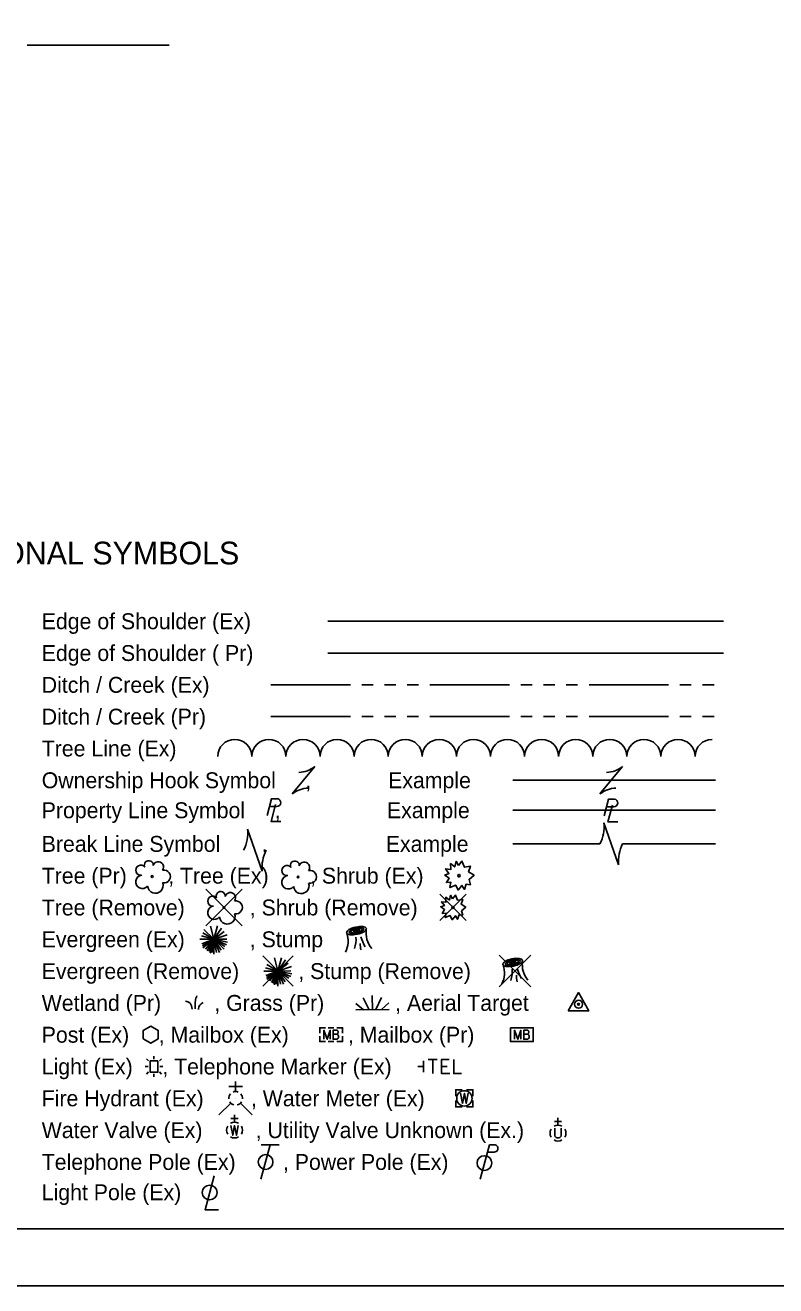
# Model space of a CAD drawing. Extents: x 0 to 34, y 0 to 22.
# Drawn here: x 7.73 to 14.34, y 0 to 11.1 of the extents above; entities that cross this region are included whole.
import ezdxf

# ---------------------------------------------------------------- set-up
doc = ezdxf.new("R2010")
doc.units = 0
for name, color, linetype in [('SH_Border', 7, 'Continuous'), ('SH_Cut_Line', 7, 'Continuous'), ('SH_Data', 7, 'Continuous'), ('SH_Text', 7, 'Continuous')]:
    doc.layers.add(name, color=color, linetype=linetype)

msp = doc.modelspace()

# ---------------------------------------------------------------- linework, layer by layer
at = {"layer": 'SH_Border'}
msp.add_lwpolyline([(1.5, 21.5), (33.5, 21.5), (33.5, 0.5), (1.5, 0.5)], close=True, dxfattribs=at)
at = {"layer": 'SH_Cut_Line'}
msp.add_lwpolyline([(0, 0), (34, 0), (34, 22), (0, 22)], close=True, dxfattribs=at)
at = {"layer": 'SH_Data'}
msp.add_line((9, 10.922), (7.75, 10.922), dxfattribs=at)
at = {"layer": 'SH_Text'}
for p, q in [((10.395, 5.85), (13.878, 5.85)), ((10.395, 5.57), (13.878, 5.57)), ((9.894, 5.29), (10.594, 5.29)), ((10.694, 5.29), (10.794, 5.29)), ((10.894, 5.29), (10.994, 5.29)), ((11.094, 5.29), (11.194, 5.29)), ((11.294, 5.29), (11.994, 5.29)), ((12.094, 5.29), (12.194, 5.29)), ((12.294, 5.29), (12.394, 5.29)), ((12.494, 5.29), (12.594, 5.29)), ((12.694, 5.29), (13.394, 5.29)), ((13.494, 5.29), (13.594, 5.29)), ((13.694, 5.29), (13.794, 5.29)), ((9.894, 5.01), (10.594, 5.01)), ((10.694, 5.01), (10.794, 5.01)), ((10.894, 5.01), (10.994, 5.01)), ((11.094, 5.01), (11.194, 5.01)), ((11.294, 5.01), (11.994, 5.01)), ((12.094, 5.01), (12.194, 5.01)), ((12.294, 5.01), (12.394, 5.01)), ((12.494, 5.01), (12.594, 5.01)), ((12.694, 5.01), (13.394, 5.01)), ((13.494, 5.01), (13.594, 5.01)), ((13.694, 5.01), (13.794, 5.01)), ((10.082, 4.33), (10.282, 4.57)), ((12.79, 4.33), (12.99, 4.57)), ((10.182, 4.45), (10.182, 4.45)), ((12.024, 4.45), (13.807, 4.45)), ((12.89, 4.45), (12.89, 4.45)), ((9.882, 4.219), (9.947, 4.219)), ((9.922, 4.188), (9.922, 4.188)), ((12.024, 4.186), (13.807, 4.186)), ((12.848, 4.215), (12.912, 4.215)), ((12.888, 4.184), (12.888, 4.184)), ((9.689, 4.019), (9.819, 3.651)), ((12.825, 4.075), (12.955, 3.706)), ((12.024, 3.89), (12.79, 3.89)), ((12.89, 3.89), (12.89, 3.89)), ((12.99, 3.89), (13.807, 3.89)), ((9.754, 3.835), (9.754, 3.835)), ((9.322, 3.491), (9.643, 3.17)), ((9.643, 3.491), (9.322, 3.17)), ((11.381, 3.446), (11.613, 3.215)), ((11.613, 3.446), (11.381, 3.215)), ((9.482, 3.33), (9.482, 3.33)), ((11.497, 3.33), (11.497, 3.33)), ((9.393, 3.05), (9.295, 3.108)), ((9.393, 3.05), (9.306, 3.137)), ((9.393, 3.05), (9.362, 3.166)), ((9.393, 3.05), (9.424, 3.168)), ((9.393, 3.05), (9.459, 3.147)), ((9.393, 3.05), (9.484, 3.12)), ((9.27, 3.05), (9.393, 3.05)), ((9.393, 3.05), (9.283, 3.08)), ((9.393, 3.05), (9.286, 3.011)), ((9.393, 3.05), (9.293, 2.993)), ((9.393, 3.05), (9.295, 2.975)), ((9.393, 3.05), (9.319, 2.964)), ((9.393, 3.05), (9.335, 2.95)), ((9.393, 3.05), (9.351, 2.942)), ((9.393, 3.05), (9.361, 2.929)), ((9.393, 3.05), (9.379, 2.935)), ((9.393, 3.05), (9.511, 3.09)), ((9.393, 3.05), (9.506, 3.052)), ((9.393, 2.919), (9.393, 3.05)), ((9.393, 3.05), (9.416, 2.934)), ((9.393, 3.05), (9.441, 2.933)), ((9.393, 3.05), (9.456, 2.955)), ((9.393, 3.05), (9.483, 2.962)), ((9.393, 3.05), (9.489, 2.986)), ((9.393, 3.05), (9.505, 3.002)), ((9.393, 3.05), (9.514, 3.026)), ((10.667, 3.05), (10.667, 3.05)), ((9.823, 2.904), (10.091, 2.637)), ((10.091, 2.904), (9.823, 2.637)), ((9.957, 2.77), (9.926, 2.886)), ((9.957, 2.77), (9.988, 2.888)), ((11.903, 2.909), (12.181, 2.631)), ((12.181, 2.909), (11.903, 2.631)), ((9.957, 2.77), (9.847, 2.8)), ((9.957, 2.77), (9.859, 2.828)), ((9.957, 2.77), (9.87, 2.858)), ((9.957, 2.77), (10.023, 2.868)), ((9.957, 2.77), (10.048, 2.841)), ((9.957, 2.77), (10.075, 2.811)), ((9.834, 2.77), (9.957, 2.77)), ((9.957, 2.77), (9.85, 2.731)), ((9.957, 2.77), (9.857, 2.713)), ((9.957, 2.77), (9.859, 2.696)), ((9.957, 2.77), (9.883, 2.684)), ((9.957, 2.77), (9.899, 2.67)), ((9.957, 2.77), (9.915, 2.662)), ((9.957, 2.77), (9.925, 2.649)), ((9.957, 2.77), (9.943, 2.656)), ((9.957, 2.77), (10.07, 2.773)), ((9.957, 2.639), (9.957, 2.77)), ((9.957, 2.77), (9.98, 2.655)), ((9.957, 2.77), (10.005, 2.654)), ((9.957, 2.77), (10.02, 2.676)), ((9.957, 2.77), (10.047, 2.682)), ((9.957, 2.77), (10.053, 2.707)), ((9.957, 2.77), (10.069, 2.722)), ((9.957, 2.77), (10.078, 2.746)), ((9.957, 2.77), (9.957, 2.77)), ((12.042, 2.77), (12.042, 2.77)), ((12.042, 2.77), (12.042, 2.77)), ((10.789, 2.43), (10.787, 2.556)), ((10.71, 2.429), (10.642, 2.486)), ((10.759, 2.43), (10.706, 2.536)), ((10.819, 2.431), (10.868, 2.538)), ((10.867, 2.432), (10.934, 2.491)), ((10.642, 2.428), (10.935, 2.433)), ((10.4, 2.272), (10.45, 2.272)), ((10.4, 2.149), (10.45, 2.149)), ((10.425, 2.21), (10.425, 2.21)), ((12.103, 2.21), (12.103, 2.21)), ((8.817, 1.979), (8.799, 1.998)), ((8.866, 1.994), (8.866, 2.021)), ((8.932, 1.998), (8.914, 1.979)), ((8.814, 1.931), (8.787, 1.931)), ((8.866, 1.93), (8.866, 1.93)), ((8.944, 1.931), (8.918, 1.931)), ((11.238, 1.93), (11.189, 1.93)), ((11.238, 1.88), (11.238, 1.98)), ((8.817, 1.882), (8.799, 1.863)), ((8.866, 1.866), (8.866, 1.84)), ((8.932, 1.863), (8.914, 1.882)), ((9.584, 1.711), (9.584, 1.797)), ((9.644, 1.754), (9.524, 1.754)), ((9.541, 1.608), (9.437, 1.504)), ((9.584, 1.65), (9.584, 1.65)), ((9.584, 1.65), (9.584, 1.65)), ((9.626, 1.608), (9.73, 1.504)), ((11.597, 1.65), (11.597, 1.65)), ((9.606, 1.472), (9.543, 1.472)), ((9.575, 1.44), (9.575, 1.504)), ((12.453, 1.446), (12.389, 1.446)), ((12.421, 1.414), (12.421, 1.478)), ((9.575, 1.37), (9.575, 1.37)), ((12.394, 1.387), (12.394, 1.318)), ((12.421, 1.344), (12.421, 1.344)), ((12.448, 1.387), (12.448, 1.318)), ((9.888, 1.24), (9.807, 0.94)), ((9.968, 1.24), (9.808, 1.24)), ((11.817, 1.24), (11.736, 0.94)), ((11.817, 1.24), (11.859, 1.24)), ((11.8, 1.177), (11.859, 1.177))]:
    msp.add_line(p, q, dxfattribs=at)
for points in [[(9.861, 4.14), (9.9, 4.288), (9.952, 4.288)], [(9.935, 4.236), (9.896, 4.088), (9.983, 4.088)], [(12.827, 4.136), (12.866, 4.284), (12.917, 4.284)], [(12.901, 4.232), (12.861, 4.084), (12.949, 4.084)], [(11.546, 3.701), (11.576, 3.738), (11.597, 3.685), (11.651, 3.694), (11.635, 3.643), (11.682, 3.614), (11.639, 3.577), (11.651, 3.531), (11.614, 3.535), (11.598, 3.489), (11.576, 3.524), (11.542, 3.483), (11.521, 3.527), (11.47, 3.506), (11.479, 3.553), (11.439, 3.549), (11.462, 3.588), (11.424, 3.616), (11.461, 3.63), (11.431, 3.67), (11.477, 3.664), (11.476, 3.716), (11.513, 3.688), (11.524, 3.737), (11.546, 3.701)], [(11.493, 3.407), (11.519, 3.439), (11.537, 3.394), (11.583, 3.401), (11.569, 3.358), (11.609, 3.333), (11.573, 3.302), (11.583, 3.263), (11.551, 3.266), (11.537, 3.227), (11.519, 3.257), (11.49, 3.222), (11.472, 3.26), (11.429, 3.241), (11.437, 3.281), (11.402, 3.278), (11.423, 3.311), (11.39, 3.336), (11.421, 3.347), (11.396, 3.381), (11.435, 3.376), (11.434, 3.42), (11.466, 3.396), (11.475, 3.438), (11.493, 3.407)], [(8.772, 2.173), (8.837, 2.135), (8.902, 2.173), (8.902, 2.248), (8.837, 2.285), (8.772, 2.248), (8.772, 2.173)], [(10.325, 2.223), (10.325, 2.272), (10.374, 2.272)], [(10.361, 2.17), (10.361, 2.25), (10.39, 2.17), (10.417, 2.25), (10.417, 2.17)], [(10.476, 2.214), (10.48, 2.217), (10.481, 2.219), (10.483, 2.221), (10.483, 2.222), (10.485, 2.225), (10.485, 2.226), (10.487, 2.231), (10.487, 2.233), (10.487, 2.235), (10.486, 2.239), (10.485, 2.242), (10.483, 2.245), (10.48, 2.247), (10.477, 2.249), (10.476, 2.249), (10.473, 2.25), (10.442, 2.25), (10.442, 2.17), (10.476, 2.17), (10.481, 2.173), (10.485, 2.176), (10.488, 2.181), (10.49, 2.187), (10.49, 2.192), (10.49, 2.196), (10.489, 2.2), (10.487, 2.206), (10.483, 2.209), (10.476, 2.214), (10.442, 2.214)], [(10.476, 2.272), (10.525, 2.272), (10.525, 2.223)], [(12.039, 2.17), (12.039, 2.25), (12.068, 2.17), (12.095, 2.25), (12.095, 2.17)], [(12.155, 2.214), (12.158, 2.217), (12.16, 2.219), (12.161, 2.221), (12.161, 2.222), (12.163, 2.225), (12.163, 2.226), (12.165, 2.231), (12.165, 2.233), (12.165, 2.235), (12.164, 2.239), (12.163, 2.242), (12.161, 2.245), (12.158, 2.247), (12.155, 2.249), (12.154, 2.249), (12.151, 2.25), (12.12, 2.25), (12.12, 2.17), (12.155, 2.17), (12.159, 2.173), (12.163, 2.176), (12.166, 2.181), (12.168, 2.187), (12.168, 2.192), (12.168, 2.196), (12.167, 2.2), (12.165, 2.206), (12.161, 2.209), (12.155, 2.214), (12.12, 2.214)], [(10.374, 2.149), (10.325, 2.149), (10.325, 2.198)], [(10.525, 2.198), (10.525, 2.149), (10.476, 2.149)], [(11.279, 1.993), (11.357, 1.993)], [(11.319, 1.993), (11.319, 1.868)], [(11.464, 1.993), (11.396, 1.993), (11.396, 1.868), (11.469, 1.868)], [(11.396, 1.931), (11.445, 1.931)], [(11.504, 1.993), (11.504, 1.868), (11.571, 1.868)], [(11.577, 1.725), (11.522, 1.725), (11.522, 1.67)], [(11.564, 1.695), (11.581, 1.605), (11.597, 1.695), (11.614, 1.605), (11.631, 1.695)], [(11.672, 1.67), (11.672, 1.725), (11.617, 1.725)], [(11.522, 1.63), (11.522, 1.575), (11.577, 1.575)], [(11.617, 1.575), (11.672, 1.575), (11.672, 1.63)], [(9.543, 1.411), (9.559, 1.325), (9.575, 1.411), (9.591, 1.325), (9.606, 1.411)], [(9.395, 0.969), (9.316, 0.67), (9.434, 0.67)]]:
    msp.add_lwpolyline(points, dxfattribs=at)
for points in [[(12.512, 2.42), (12.692, 2.42), (12.602, 2.581)], [(12.003, 2.272), (12.203, 2.272), (12.203, 2.149), (12.003, 2.149)], [(8.832, 1.88), (8.899, 1.88), (8.899, 1.98), (8.832, 1.98)]]:
    msp.add_lwpolyline(points, close=True, dxfattribs=at)
for centre, radius in [((8.849, 3.602), 0.0084), ((10.134, 3.599), 0.0072), ((11.55, 3.61), 0.0115), ((9.482, 3.33), 0.0072), ((11.497, 3.33), 0.00979), ((12.602, 2.478), 0.035), ((12.602, 2.478), 0.008), ((11.597, 1.65), 0.0675), ((9.848, 1.09), 0.065), ((11.774, 1.08), 0.065), ((9.356, 0.821), 0.065)]:
    msp.add_circle(centre, radius, dxfattribs=at)
for centre, radius, start, end in [((9.577, 4.66), 0.15, 0.0098, 179.9926), ((9.877, 4.66), 0.15, 0.0098, 179.9926), ((10.177, 4.66), 0.15, 0.0098, 179.9926), ((10.477, 4.66), 0.15, 0.0098, 179.9926), ((10.777, 4.66), 0.15, 0.0098, 179.9926), ((11.077, 4.66), 0.15, 0.0098, 179.9926), ((11.377, 4.66), 0.15, 0.0098, 179.9926), ((11.677, 4.66), 0.15, 0.0098, 179.9926), ((11.977, 4.66), 0.15, 0.0098, 179.9926), ((12.277, 4.66), 0.15, 0.0098, 179.9926), ((12.577, 4.66), 0.15, 0.0098, 179.9926), ((12.877, 4.66), 0.15, 0.0098, 179.9926), ((13.177, 4.66), 0.15, 0.0098, 179.9926), ((13.477, 4.66), 0.15, 0.0098, 179.9926), ((13.777, 4.66), 0.15, 89.9955, 179.9926), ((10.124, 4.785), 0.267, 273.6945, 306.337), ((12.832, 4.785), 0.267, 273.6945, 306.337), ((10.24, 4.115), 0.267, 93.6945, 126.337), ((12.948, 4.115), 0.267, 93.6945, 126.337), ((9.947, 4.254), 0.0345, 270.471, 81.3281), ((12.912, 4.25), 0.0345, 270.471, 81.3281), ((9.357, 3.987), 0.334, 332.9422, 5.5848), ((12.493, 4.042), 0.334, 332.9422, 5.5848), ((13.287, 3.739), 0.334, 152.9422, 185.5848), ((10.151, 3.683), 0.334, 152.9422, 185.5848), ((8.75, 3.658), 0.0441, 39.0625, 279.5412), ((8.82, 3.703), 0.0395, 354.0047, 205.9741), ((8.904, 3.687), 0.0466, 323.83, 165.0376), ((10.035, 3.655), 0.0441, 39.0625, 279.5412), ((10.105, 3.7), 0.0395, 354.0047, 205.9741), ((10.189, 3.684), 0.0466, 323.83, 165.0376), ((8.764, 3.556), 0.0592, 96.1722, 320.5737), ((8.953, 3.603), 0.0574, 259.1453, 101.4596), ((10.048, 3.552), 0.0592, 96.1722, 320.5737), ((10.238, 3.6), 0.0574, 259.1453, 101.4596), ((8.878, 3.524), 0.0685, 184.9476, 19.4572), ((9.453, 3.431), 0.0395, 354.0047, 205.9741), ((9.537, 3.415), 0.0466, 323.83, 165.0376), ((10.162, 3.521), 0.0685, 184.9476, 19.4572), ((9.397, 3.284), 0.0592, 96.1722, 320.5737), ((9.383, 3.386), 0.0441, 39.0625, 279.5412), ((9.586, 3.331), 0.0574, 259.1453, 101.4596), ((9.511, 3.252), 0.0685, 184.9476, 19.4572), ((10.947, 3.107), 0.215, 171.4106, 219.9194), ((10.375, 3.033), 0.2, 331.5338, 20.9269), ((10.391, 3.052), 0.253, 340.7938, 3.5481), ((10.862, 3.01), 0.182, 178.7926, 197.1224), ((10.992, 3.153), 0.316, 194.9653, 212.1216), ((11.751, 2.753), 0.2, 331.5338, 20.9269), ((11.766, 2.772), 0.253, 340.7938, 3.5481), ((12.368, 2.873), 0.316, 194.9653, 212.1216), ((12.322, 2.827), 0.215, 171.4106, 219.9194), ((12.237, 2.73), 0.182, 178.7926, 197.1224), ((9.584, 1.65), 0.06, 140.021, 184.0629), ((9.584, 1.65), 0.06, 68.1395, 112.038), ((9.584, 1.65), 0.06, 356.0165, 39.9889), ((9.584, 1.65), 0.06, 211.8788, 255.8479), ((9.584, 1.65), 0.06, 283.8239, 329.9097), ((9.575, 1.371), 0.07, 150.0184, 209.9816), ((9.575, 1.371), 0.07, 60.0184, 120.0157), ((9.575, 1.371), 0.07, 330.0184, 29.9816), ((12.421, 1.344), 0.07, 150.0184, 209.9816), ((12.421, 1.344), 0.07, 60.0184, 120.0157), ((12.421, 1.344), 0.07, 330.0184, 29.9816), ((9.575, 1.371), 0.07, 239.9843, 299.9816), ((11.86, 1.209), 0.0319, 268.8767, 91.1233), ((12.421, 1.344), 0.07, 239.9843, 299.9816), ((12.421, 1.331), 0.03, 205.1924, 334.8076)]:
    msp.add_arc(centre, radius, start, end, dxfattribs=at)
for centre, major_axis in [((10.648, 3.126), (0.0868, 0.0187)), ((10.648, 3.126), (0.0651, 0.0141)), ((10.648, 3.126), (0.0488, 0.0105)), ((10.648, 3.126), (0.0275, 0.0059)), ((10.648, 3.126), (0.0154, 0.0033)), ((12.023, 2.846), (0.0868, 0.0187)), ((12.023, 2.846), (0.0651, 0.0141)), ((12.023, 2.846), (0.0488, 0.0105)), ((12.023, 2.846), (0.0275, 0.0059)), ((12.023, 2.846), (0.0154, 0.0033))]:
    msp.add_ellipse(centre, major_axis=major_axis, ratio=0.36865, dxfattribs=at)
for points in [[(9.142, 2.506), (9.183, 2.488), (9.201, 2.435)], [(9.229, 2.439), (9.229, 2.486), (9.235, 2.531), (9.244, 2.551)], [(9.257, 2.432), (9.269, 2.47), (9.298, 2.494)]]:
    msp.add_spline(points, degree=3, dxfattribs=at)

# ---------------------------------------------------------------- texts
for s, height, p in [('CONVENTIONAL SYMBOLS', 0.2, (6.139, 6.35)), ('Edge of Shoulder (Ex)', 0.14, (7.878, 5.78)), ('Edge of Shoulder ( Pr)', 0.14, (7.878, 5.5)), ('Ditch / Creek (Ex)', 0.14, (7.878, 5.22)), ('Ditch / Creek (Pr)', 0.14, (7.878, 4.94)), ('Tree Line (Ex)', 0.14, (7.878, 4.66)), ('Ownership Hook Symbol     ,             Example', 0.14, (7.878, 4.38)), ('Property Line Symbol     ,                  Example', 0.14, (7.878, 4.116)), ('Break Line Symbol       ,                    Example', 0.14, (7.878, 3.82)), ('Tree (Pr)       , Tree (Ex)       , Shrub (Ex)', 0.14, (7.878, 3.54)), ('Tree (Remove)           , Shrub (Remove)', 0.14, (7.878, 3.26)), ('Evergreen (Ex)           , Stump ', 0.14, (7.878, 2.98)), ('Evergreen (Remove)          , Stump (Remove)', 0.14, (7.878, 2.7)), ('Wetland (Pr)         , Grass (Pr)            , Aerial Target    ', 0.14, (7.878, 2.42)), ('Post (Ex)     , Mailbox (Ex)          , Mailbox (Pr)', 0.14, (7.878, 2.14)), ('Light (Ex)     , Telephone Marker (Ex)     ', 0.14, (7.878, 1.86)), ('Fire Hydrant (Ex)        , Water Meter (Ex)', 0.14, (7.878, 1.58)), ('Water Valve (Ex)         , Utility Valve Unknown (Ex.)', 0.14, (7.878, 1.3)), ('Telephone Pole (Ex)        , Power Pole (Ex)', 0.14, (7.878, 1.02)), ('Light Pole (Ex)     ', 0.14, (7.878, 0.753))]:
    msp.add_text(s, height=height, dxfattribs=at).set_placement(p)

doc.saveas('drawing.dxf')
